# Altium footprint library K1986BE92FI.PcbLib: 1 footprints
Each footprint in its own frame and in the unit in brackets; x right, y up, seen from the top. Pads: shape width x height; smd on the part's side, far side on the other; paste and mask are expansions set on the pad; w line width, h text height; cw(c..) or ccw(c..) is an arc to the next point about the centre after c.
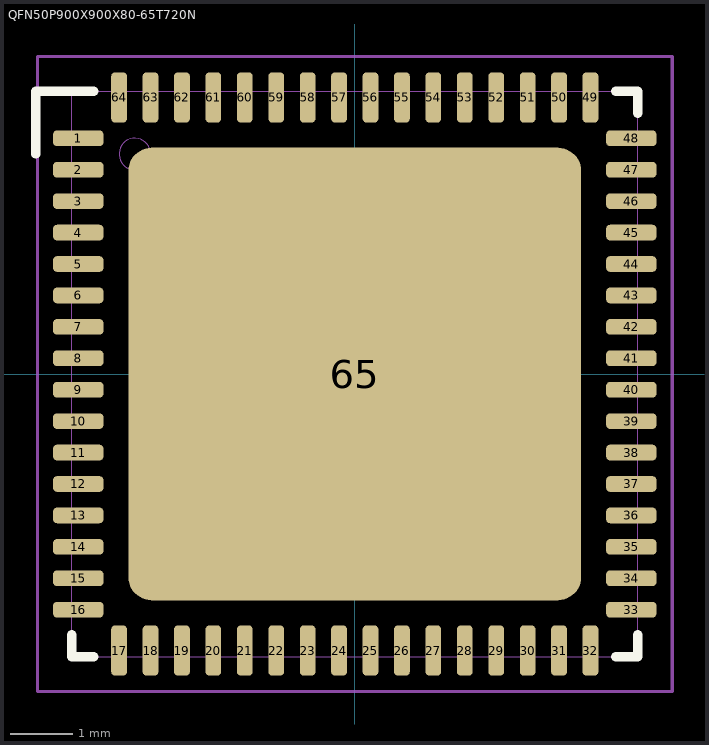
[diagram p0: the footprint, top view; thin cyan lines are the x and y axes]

## QFN50P900X900X80-65T720N [mm] "64-QFN, 0.50 mm pitch, 9.00 X 9.00 X 0.80 mm body, 7.20 X 7.20 mm thermal pad"
height 0.8
pads (65):
  rrect50% 0.8x0.25 smd mask+0.05: 1(-4.4,3.75) 2(-4.4,3.25) 3(-4.4,2.75) 4(-4.4,2.25) 5(-4.4,1.75) 6(-4.4,1.25) 7(-4.4,0.75) 8(-4.4,0.25) 9(-4.4,-0.25) 10(-4.4,-0.75) 11(-4.4,-1.25) 12(-4.4,-1.75) 13(-4.4,-2.25) 14(-4.4,-2.75) 15(-4.4,-3.25) 16(-4.4,-3.75) 33(4.4,-3.75) 34(4.4,-3.25) 35(4.4,-2.75) 36(4.4,-2.25) 37(4.4,-1.75) 38(4.4,-1.25) 39(4.4,-0.75) 40(4.4,-0.25) 41(4.4,0.25) 42(4.4,0.75) 43(4.4,1.25) 44(4.4,1.75) 45(4.4,2.25) 46(4.4,2.75) 47(4.4,3.25) 48(4.4,3.75)
  rrect50% 0.25x0.8 smd mask+0.05: 17(-3.75,-4.4) 18(-3.25,-4.4) 19(-2.75,-4.4) 20(-2.25,-4.4) 21(-1.75,-4.4) 22(-1.25,-4.4) 23(-0.75,-4.4) 24(-0.25,-4.4) 25(0.25,-4.4) 26(0.75,-4.4) 27(1.25,-4.4) 28(1.75,-4.4) 29(2.25,-4.4) 30(2.75,-4.4) 31(3.25,-4.4) 32(3.75,-4.4) 49(3.75,4.4) 50(3.25,4.4) 51(2.75,4.4) 52(2.25,4.4) 53(1.75,4.4) 54(1.25,4.4) 55(0.75,4.4) 56(0.25,4.4) 57(-0.25,4.4) 58(-0.75,4.4) 59(-1.25,4.4) 60(-1.75,4.4) 61(-2.25,4.4) 62(-2.75,4.4) 63(-3.25,4.4) 64(-3.75,4.4)
  rrect10% 7.2x7.2 smd paste-2539.97 mask+0.05: 65(0,0)
Top Overlay:
  lines w0.15: -5.075,3.5 -5.075,4.5 ; -5.05,4.5 -4.15,4.5 ; -4.5,-4.15 -4.5,-4.5 -4.15,-4.5 ; 4.15,-4.5 4.5,-4.5 4.5,-4.15 ; 4.15,4.5 4.5,4.5 4.5,4.15
Top Paste:
  drawing of 25 lines, arcs and shapes, not listed
Top Assembly:
  circle w0: c-3.5,3.5 r0.25
  lines w0: -4.5,-4.5 4.5,-4.5 4.5,4.5 -4.5,4.5 -4.5,-4.5
  text ".Designator" at -2.621,-0.355 h1.52
Top Courtyard:
  lines w0.05: -5.05,-5.05 5.05,-5.05 5.05,5.05 -5.05,5.05 -5.05,-5.05
3D body "QFN50P900X900X80-65T720N.STEP": height 0.75, standoff 0, extent -4.5,-4.5 4.5,4.5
